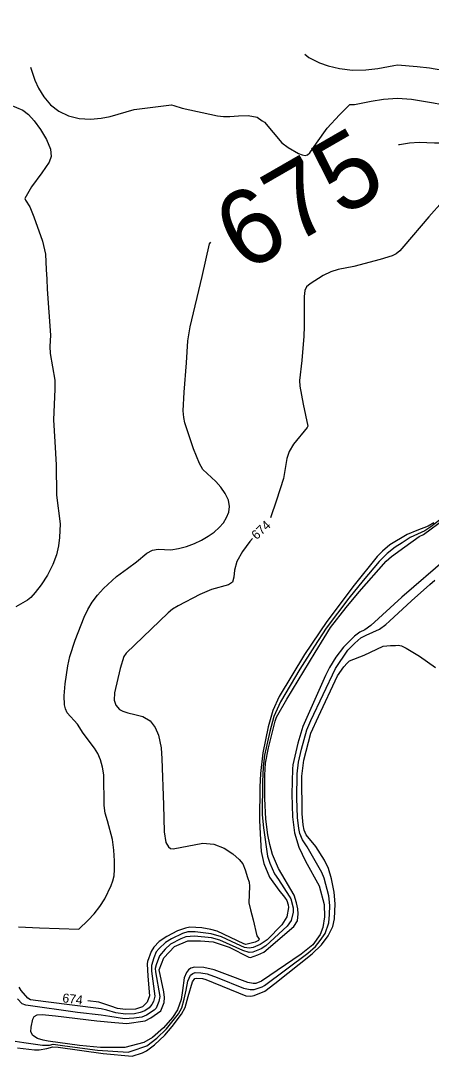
# Model space of a CAD drawing. Extents: x -291892836 to 2945206, y -477993085 to 1832792.
# Drawn here: x 1851834.7 to 1852014.8, y 544784.1 to 545237.9 of the extents above; entities that cross this region are included whole.
import ezdxf

# ---------------------------------------------------------------- set-up
doc = ezdxf.new("R2010")
doc.units = 0
for name, color, linetype in [('DT_X_Contour_Minor', 7, 'Continuous'), ('DT_X_Terrain_Ground_Line', 7, 'Continuous'), ('Level 19', 7, 'Continuous')]:
    doc.layers.add(name, color=color, linetype=linetype)

msp = doc.modelspace()

# ---------------------------------------------------------------- linework, layer by layer
at = {"layer": 'DT_X_Contour_Minor'}
for points in [[(1852000.48, 545183.63), (1852000.85, 545183.73), (1852005.19, 545184.37), (1852009.54, 545184.66), (1852016.21, 545184.47), (1852018.57, 545184.37), (1852021.02, 545184.7), (1852031.16, 545187.8), (1852034.87, 545188.22), (1852041.86, 545188.51), (1852047.52, 545189.7), (1852050.86, 545190.56), (1852056.14, 545191.11), (1852071.24, 545193.49), (1852075.35, 545194.47), (1852076.82, 545195.05), (1852080.88, 545197.48), (1852088.26, 545202.57), (1852090.65, 545205.91), (1852094.39, 545212.49), (1852102.07, 545228.46), (1852106.84, 545237.93)], [(1851959.3, 545223.31), (1851961.05, 545221.87), (1851964.56, 545220.04)], [(1851964.56, 545220.04), (1851965.74, 545219.43), (1851969.55, 545218.15), (1851974.56, 545216.94), (1851980.25, 545216.25), (1851986.07, 545216.38), (1851991.32, 545217.03), (1851998.33, 545218.33), (1852000.01, 545218.58), (1852008.6, 545217.88), (1852013.95, 545217.27), (1852019.87, 545216.2)], [(1851806.65, 545217.01), (1851809.35, 545214.32), (1851814.28, 545210), (1851819.51, 545206.16), (1851824.48, 545203.4), (1851835.65, 545198.67), (1851838.16, 545196.84), (1851840.69, 545194.11), (1851843.5, 545190.23), (1851846.08, 545185.81), (1851847.77, 545181.69), (1851848.07, 545178.46), (1851847.25, 545175.93), (1851843.98, 545171.31), (1851839.49, 545165.06), (1851836.55, 545160.03), (1851836.78, 545159.34), (1851838.7, 545156.33), (1851840.49, 545151.98), (1851844.26, 545141.25), (1851845.55, 545135.66), (1851845.97, 545128.96), (1851846.14, 545124.67)], [(1851839.01, 545217.61), (1851840.93, 545211.92), (1851842.58, 545208.34), (1851844.88, 545204.58), (1851847.86, 545201.08), (1851851.52, 545198.23), (1851855.77, 545196.19), (1851860.44, 545195.03), (1851865.35, 545194.77), (1851870.02, 545195.17), (1851873.91, 545195.93), (1851884.56, 545198.96), (1851900.81, 545201.09), (1851901.94, 545200.74), (1851905.55, 545199.64), (1851921.05, 545196.26), (1851923.62, 545195.9), (1851926.51, 545195.93), (1851930.31, 545196.29), (1851934.55, 545196.41), (1851938.5, 545195.6), (1851940.71, 545194.06)], [(1851940.71, 545194.06), (1851941.65, 545193.41), (1851949.29, 545184.45), (1851951.97, 545182.34), (1851956.53, 545179.71), (1851958.21, 545179.12), (1851959.53, 545178.93), (1851960.57, 545179.15), (1851961.57, 545179.96), (1851964.52, 545184.21), (1851969.19, 545190.84), (1851974.56, 545196.71), (1851979.13, 545201.14), (1851981.17, 545201.17), (1851988.38, 545202.71), (1851993.84, 545203.56), (1851999.98, 545203.97), (1852006.11, 545203.62), (1852015.78, 545201.98), (1852021.93, 545200.83), (1852023.7, 545200.6)], [(1852019.75, 545158.64), (1852013.67, 545152.03), (1852002.7, 545139.17), (1852000.94, 545137.1), (1851999.45, 545135.8), (1851997.68, 545134.88), (1851992.43, 545133.25), (1851980.79, 545130.17), (1851973.97, 545128.86), (1851970.72, 545127.84), (1851967.34, 545126.22), (1851961.67, 545122.61), (1851960.14, 545121.29), (1851959.4, 545119.74), (1851959.11, 545117.11), (1851959.03, 545103.97), (1851958.96, 545099.62), (1851958.02, 545088.98), (1851956.95, 545080.26), (1851957.12, 545077.74), (1851958.65, 545069.82), (1851960.67, 545060.22), (1851960.4, 545059.58), (1851954.4, 545052.32), (1851952.53, 545049.17), (1851951.48, 545046.06), (1851950.01, 545037.29), (1851946.93, 545027.74), (1851944.32, 545020.12)], [(1851833.83, 544840.85), (1851842.95, 544840.41), (1851860.27, 544839.77), (1851864.26, 544843.69), (1851866.89, 544846.54), (1851869.49, 544849.78), (1851871.62, 544853.11), (1851874.42, 544858.92), (1851875.21, 544861.03), (1851875.69, 544863.12), (1851875.9, 544865.88), (1851875.89, 544869.79), (1851875.61, 544874.43), (1851874.95, 544879.14), (1851872.77, 544887.2), (1851871.84, 544890.66), (1851871.4, 544893.91), (1851871.15, 544907.41), (1851870.62, 544910.85), (1851869.71, 544914.02), (1851868.51, 544916.81), (1851867.18, 544919.08), (1851862.17, 544925.68), (1851859.61, 544929.67), (1851855.19, 544934.62), (1851854.35, 544936.34), (1851853.91, 544938.17), (1851853.75, 544942.09), (1851854.22, 544947.36), (1851855.39, 544955.19), (1851856.28, 544959.29), (1851858.63, 544966.45), (1851862.53, 544976.51), (1851864.13, 544979.84), (1851866.09, 544983.07), (1851868.4, 544986.17), (1851871.01, 544989.12), (1851876.69, 544994.33), (1851881.57, 544997.92), (1851885.6, 545000.8), (1851890.08, 545004.59), (1851892.5, 545005.9), (1851895, 545006.28), (1851900.64, 545006.07), (1851903.97, 545006.55), (1851907.48, 545007.54), (1851910.92, 545008.85), (1851914.1, 545010.33), (1851916.98, 545011.97), (1851919.53, 545013.78), (1851921.77, 545015.76), (1851923.63, 545017.89), (1851925.07, 545020.14), (1851926.03, 545022.5), (1851926.34, 545025.01), (1851925.84, 545027.74), (1851924.45, 545030.68), (1851922.47, 545033.56), (1851920.28, 545036.01), (1851914.63, 545041.27), (1851913.13, 545043.85), (1851910.56, 545050.3), (1851906.74, 545061.68), (1851906.23, 545064.07), (1851906.03, 545066.98), (1851906.5, 545075.11), (1851907.44, 545087.98), (1851908.01, 545097.58), (1851909.12, 545103.82), (1851914.33, 545125.85), (1851917.6, 545140.1), (1851918.15, 545140.94)], [(1851846.14, 545124.67), (1851846.32, 545120.28), (1851847.79, 545100.13), (1851847.5, 545095.11), (1851847.68, 545092.08), (1851849.66, 545080.37), (1851849.77, 545076.47), (1851849.17, 545062.98), (1851849.72, 545053.34), (1851850.33, 545043.34), (1851850.45, 545029.99), (1851852.03, 545017.44), (1851851.78, 545011.38), (1851851.31, 545007.82), (1851850.4, 545003.86), (1851848.81, 544999.54), (1851846.43, 544995), (1851843.69, 544990.73), (1851841.15, 544987.32), (1851839.22, 544985.17), (1851837.71, 544983.93), (1851832.57, 544981.1)], [(1852020.37, 545020.55), (1852014.62, 545016.04), (1852011.95, 545014.35), (1852005.55, 545011.45), (1852002.09, 545009.17), (1851998.94, 545007.16), (1851995.49, 545004.46), (1851991.95, 545000.93), (1851984.92, 544992.55), (1851978.71, 544984.92), (1851968.73, 544971.68), (1851963.55, 544963.86), (1851957.21, 544953.71), (1851948.73, 544939.36), (1851945.73, 544933.02), (1851943.95, 544926.38), (1851941.7, 544916.05), (1851941.06, 544910.95), (1851940.77, 544904.32), (1851940.7, 544889.93), (1851941.27, 544884.18), (1851942.93, 544871.78), (1851944.02, 544868.73), (1851946.11, 544863.99), (1851947.79, 544861.57), (1851952.54, 544854.25), (1851953.28, 544853.06), (1851954.26, 544849.14), (1851954.22, 544847.27), (1851953.36, 544843.58), (1851951.59, 544841.03), (1851942.2, 544832.54), (1851940.2, 544831.15), (1851936.49, 544829.72), (1851934.89, 544829.48), (1851932.23, 544830.41), (1851922.08, 544834.95), (1851918.44, 544836), (1851910.9, 544836.71), (1851907.23, 544836.44), (1851904.98, 544835.47), (1851900.39, 544833.18), (1851898.08, 544830.95), (1851895.64, 544828.13), (1851894.18, 544824.2), (1851893.74, 544822.5), (1851893.84, 544821.02), (1851895.7, 544810.25), (1851895.33, 544808.02), (1851894.09, 544805.1), (1851893.22, 544804.29), (1851889.93, 544802.14), (1851887.81, 544801.24), (1851884.31, 544800.71), (1851880.31, 544800.48), (1851873.77, 544801.46), (1851870.03, 544802.15), (1851859.7, 544803.24), (1851836.99, 544806.43), (1851835.4, 544807.11)], [(1851919.11, 544834.18), (1851926.1, 544831.83), (1851934.84, 544827.53), (1851935.52, 544827.42), (1851938.74, 544828.53), (1851941.35, 544829.74), (1851954.59, 544840.95), (1851956.08, 544843.49), (1851956.42, 544846.54), (1851956.29, 544848.63), (1851955.76, 544851.26), (1851954.69, 544854.7), (1851947.74, 544866.4), (1851945.13, 544872.54), (1851944.01, 544876.88), (1851943.19, 544881.07), (1851942.25, 544887.95), (1851941.8, 544897.05), (1851941.86, 544907.24), (1851942.05, 544912.47), (1851943.36, 544919.24), (1851946.28, 544931), (1851946.99, 544932.76), (1851951.44, 544940.63), (1851963.84, 544961.05), (1851967.76, 544967.43), (1851970.66, 544971.96), (1851977.48, 544980.75), (1851983.19, 544987.67), (1851995.02, 545001.09), (1851997.3, 545003.15), (1852003.2, 545007.3), (1852009.54, 545011.82), (1852011.41, 545012.75), (1852020.94, 545019.76)], [(1852015.9, 545017.93), (1852013.37, 545016.47), (1852008.51, 545014.53), (1852004.22, 545012.79), (1851996.66, 545008.28), (1851993.42, 545005.43), (1851991.11, 545003.12), (1851981.03, 544990.59), (1851969.03, 544974.57), (1851959.2, 544960.18), (1851948.04, 544941.78), (1851945.32, 544935.57), (1851943.3, 544928.4), (1851940.88, 544917.07), (1851939.93, 544908), (1851939.66, 544902.03), (1851939.44, 544887.62), (1851939.82, 544881.56), (1851940.25, 544873.86), (1851941.39, 544868.49), (1851943.83, 544862.58), (1851947.94, 544856.8), (1851950.38, 544853.8), (1851951.45, 544852.37), (1851952.06, 544850.46), (1851952.22, 544849.24), (1851951.45, 544845.23), (1851949.28, 544841.63), (1851942.8, 544835.08), (1851939.77, 544833.06), (1851936.73, 544831.81), (1851934.94, 544831.44), (1851932.83, 544831.76), (1851929.32, 544833.4), (1851922.86, 544836.4), (1851918.28, 544837.79), (1851911.31, 544838.63), (1851908.09, 544838.54), (1851905.76, 544837.92), (1851900.81, 544835.59), (1851898.28, 544833.98), (1851895.44, 544831.29), (1851894.2, 544829.8), (1851893.1, 544827.24), (1851892.06, 544823.9), (1851892.09, 544821.36), (1851893.53, 544810.4), (1851892.95, 544808.14), (1851892.31, 544806.7), (1851891.08, 544805.35), (1851889.14, 544804.01), (1851887.2, 544803.2), (1851884.7, 544802.71), (1851880.72, 544802.53), (1851876.49, 544803.09), (1851872.57, 544804.23), (1851869.98, 544804.87), (1851845.83, 544807.87), (1851839.08, 544808.83), (1851837.93, 544809.54), (1851834.93, 544812.92), (1851834.09, 544814.41)], [(1851936.44, 545010.98), (1851935.23, 545009.62), (1851931.98, 545005.33), (1851929.55, 545000.94), (1851928.56, 544997.08), (1851928.28, 544994.01), (1851927.66, 544991.87), (1851925.84, 544990.68), (1851918.43, 544988.58), (1851913.25, 544986.42), (1851903.86, 544981.53), (1851901.31, 544979.97), (1851899.43, 544978.43), (1851881.01, 544960.81), (1851879.95, 544959.3), (1851878.43, 544953.98), (1851875.89, 544943.37), (1851875.73, 544940.18), (1851876.49, 544937.96), (1851878.07, 544936.07), (1851879.47, 544935.25), (1851881.67, 544934.55), (1851884.82, 544933.92), (1851888.34, 544932.95), (1851891.52, 544931.15), (1851893.77, 544928.23), (1851895.17, 544924.79), (1851896.39, 544919.27), (1851896.71, 544914.4), (1851897.32, 544894.26), (1851897.66, 544882.48), (1851898.46, 544877.82), (1851899.52, 544875.79), (1851900.4, 544875.14), (1851901.59, 544875.02), (1851914.65, 544877.47), (1851919.47, 544877.02), (1851923.96, 544875.28), (1851927.77, 544872.78), (1851930.56, 544870.28), (1851932.13, 544868.36), (1851933.14, 544865.77), (1851934.22, 544862.44), (1851934.94, 544860.32), (1851935.08, 544858.65), (1851934.82, 544851.37), (1851935.54, 544848.28), (1851936.69, 544843.82), (1851938.23, 544836.9), (1851938.98, 544835.84), (1851939.39, 544835.37), (1851938.97, 544834.81), (1851937.51, 544834.04), (1851933.43, 544833.11), (1851932.64, 544833.34), (1851920.85, 544838.88), (1851918.11, 544839.69), (1851914.25, 544840.35), (1851908.85, 544840.59), (1851907, 544840.26), (1851903.5, 544839.04), (1851898.84, 544836.59), (1851895.53, 544834.34), (1851893.13, 544831.9), (1851892.02, 544830.06), (1851890.37, 544825.65), (1851890.24, 544824.54), (1851890.56, 544819.24), (1851891.26, 544810.57), (1851890.25, 544807.85), (1851888.19, 544805.81), (1851885.1, 544804.71), (1851880.66, 544804.62), (1851877.24, 544805.06), (1851874.23, 544806.08), (1851869.07, 544807.78), (1851864.23, 544808.37)], [(1852021.9, 545002.57), (1852001.84, 544985.23), (1851988.3, 544972.94), (1851985.59, 544971.04), (1851983.42, 544970.01), (1851981.13, 544968.14), (1851976.37, 544963.44), (1851972.93, 544959.01), (1851970.15, 544954.48), (1851968.43, 544950.98), (1851958.45, 544928.64), (1851956.35, 544921.3), (1851954.11, 544911.83), (1851953.89, 544910.12), (1851953.68, 544898.89), (1851953.95, 544889.02), (1851954.83, 544881.96), (1851956.72, 544875.67), (1851959.7, 544869.61), (1851965.66, 544858.82), (1851967.83, 544850.55), (1851967.92, 544845.23), (1851967.27, 544840.53), (1851966.13, 544837.51), (1851962.83, 544832.85), (1851957.78, 544828.83), (1851940.31, 544816.94), (1851937.81, 544816.03), (1851936.71, 544816.03), (1851934.38, 544816.42), (1851925.45, 544819.77), (1851919.54, 544821.97), (1851915.1, 544822.98), (1851910.97, 544823.19), (1851909.32, 544822.67), (1851908.31, 544821.93), (1851907.47, 544820.84), (1851906.44, 544818.4), (1851905.63, 544812.83), (1851905.05, 544808.99), (1851903.52, 544804.47), (1851901.3, 544801.04), (1851897.41, 544796.56), (1851892.57, 544792.35), (1851888.8, 544790.04), (1851880.44, 544787.86), (1851869.68, 544787.93), (1851860.57, 544788.73), (1851846.82, 544790.71), (1851844.6, 544791.13), (1851842.08, 544791.9), (1851840.09, 544793.12), (1851839.25, 544794.85), (1851839.28, 544796.84), (1851840.07, 544800.37), (1851840.72, 544801.53), (1851842, 544802.2), (1851844.13, 544802.38), (1851850.04, 544801.84), (1851868.1, 544799.54), (1851876.09, 544798.86), (1851881.32, 544798.39), (1851889.28, 544799.54), (1851891.81, 544800.9), (1851896.21, 544803.95), (1851897.61, 544807.64), (1851897.85, 544809.82), (1851897.58, 544812.28), (1851895.49, 544821.93), (1851897.51, 544827.27), (1851902.17, 544832.13), (1851908.1, 544834.69), (1851913.6, 544834.68), (1851919.11, 544834.18)], [(1851832.34, 544790.64), (1851836.16, 544790.09), (1851844.36, 544788.89), (1851847.41, 544788.99), (1851849.02, 544789.34), (1851854.06, 544788.62), (1851868.38, 544786.78), (1851881.83, 544785.93), (1851883.23, 544786.34), (1851890.05, 544788.63), (1851894.48, 544791.97), (1851898.68, 544796.11), (1851903.89, 544802.7), (1851905.36, 544805.37), (1851906.49, 544809.1), (1851907.28, 544813.04), (1851908.01, 544817.06), (1851909.28, 544819.61), (1851910.23, 544820.41), (1851911.3, 544820.75), (1851913.69, 544820.69), (1851916.55, 544820.19), (1851920.87, 544818.58), (1851932.4, 544813.98), (1851935.33, 544813.27), (1851937.18, 544813.33), (1851940.63, 544814.54), (1851941.67, 544815.14), (1851960.72, 544829.22), (1851964.05, 544832.19), (1851966.13, 544834.78), (1851968.2, 544837.95), (1851969.88, 544842.49), (1851970.24, 544846.14), (1851970.25, 544850.12), (1851969.81, 544854.39), (1851967.83, 544862.19), (1851966.74, 544864.63), (1851960.43, 544875.85), (1851958.26, 544878.87), (1851957.23, 544881.64), (1851956.66, 544883.96), (1851956.09, 544888.67), (1851955.88, 544897.22), (1851955.97, 544907.8), (1851956.52, 544912.94), (1851957.89, 544918.69), (1851960.19, 544927.14), (1851961.93, 544931.2), (1851972.78, 544954.08), (1851978.28, 544962.04), (1851981.22, 544965.15), (1851983.94, 544967.44), (1851986.29, 544968.64), (1851992.09, 544971.23), (1851994.8, 544973.32), (1851996.45, 544974.84), (1852006.15, 544983.68), (1852014.18, 544990.81), (1852016.35, 544992.72)], [(1851833.36, 544787.81), (1851840.81, 544786.96), (1851842.84, 544786.91), (1851846.23, 544787.52), (1851848.87, 544788.25), (1851851.19, 544788.03), (1851870.98, 544785.32), (1851883.62, 544784.06), (1851888.1, 544785.58), (1851889.95, 544786.47), (1851893.43, 544789.07), (1851897.97, 544793.31), (1851901.17, 544797.17), (1851905.19, 544802.47), (1851906.82, 544805.4), (1851908.21, 544810.21), (1851910.14, 544816.76), (1851911.13, 544818.16), (1851912.06, 544818.32), (1851914.45, 544818.15), (1851915.91, 544817.67), (1851933.48, 544810.62), (1851935.69, 544810.39), (1851937.12, 544810.68), (1851941.82, 544812.57), (1851946.18, 544815.92), (1851962.63, 544828.97), (1851966.67, 544832.96), (1851969.64, 544836.87), (1851971.56, 544840.98), (1851972.37, 544844.3), (1851972.62, 544850.81), (1851972.2, 544855.94), (1851971.01, 544861.78), (1851969.73, 544866.3), (1851967.94, 544870.09), (1851964.15, 544876.03), (1851959.9, 544881.16), (1851959.02, 544883.16), (1851958.56, 544885.53), (1851958.16, 544890.34), (1851958.1, 544906.85), (1851958.87, 544913.83), (1851961.94, 544925.64), (1851965.31, 544932.95), (1851973.66, 544950.76), (1851976.41, 544954.68), (1851977.85, 544956.42), (1851979, 544957.35), (1851985.39, 544959.84), (1851993.74, 544963.86), (1851996.92, 544964.06), (1851999.16, 544964.16), (1852000.22, 544964.24), (1852001.7, 544963.93), (1852003.85, 544962.99), (1852009.7, 544959.5), (1852016.68, 544954.46)], [(1851835.4, 544807.11), (1851833.3, 544809.18)]]:
    msp.add_lwpolyline(points, dxfattribs=at)

# ---------------------------------------------------------------- texts
at = {"layer": 'DT_X_Terrain_Ground_Line'}
msp.add_text('675', height=33, rotation=29.9256, dxfattribs=at).set_placement((1851932.85, 545127.18))
at = {"layer": 'Level 19'}
for rotation, p in [(42.8572, (1851938.19, 545010.24)), (353.0165, (1851852.86, 544807.75))]:
    msp.add_text('674', height=4, rotation=rotation, dxfattribs=at).set_placement(p)

doc.saveas('drawing.dxf')
